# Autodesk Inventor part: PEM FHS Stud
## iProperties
Author: John A. Hunter
Shininess: 64.0
Angle Display Precision: 2
Document Length Units: 11272
Document Angle Units: 11286
Document Time Units: 11279
Document Mass Units: 11290
Document Length Units Precision: 3
Document Angle Units Precision: 2
Compacted: True
PropertySet Name: _Private Model Information
Created: 2002-08
Part Number: PEM FHS Stud
Material: Stainless Steel, 440C
Description: FHS-256-4
Document SubType Name: Modeling
Designer: John A. Hunter
Control State: 0
Master: False
Checked Out: False
PropertySet Name: Design Tracking Control
Density: 0.0
Volumn: 0.0
Area: 0.0
PropertySet Name: Model Information
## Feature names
1. Extrusion1
2. Extrusion2
